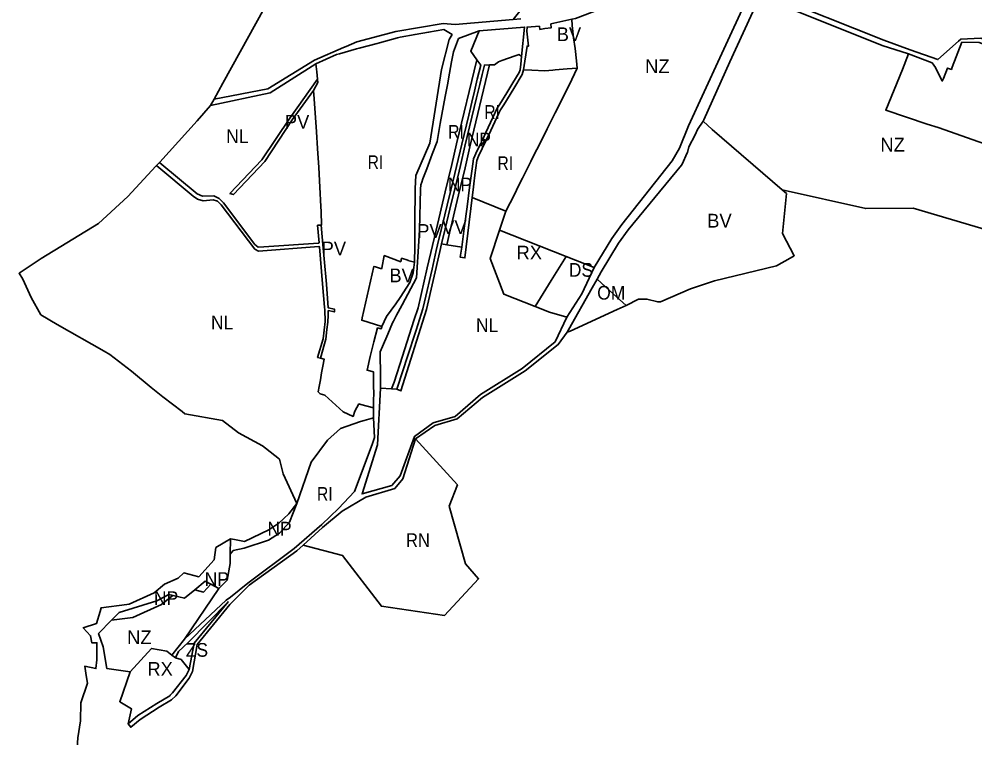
# Model space of a CAD drawing. Extents: x -650451 to -642268, y -1075216 to -1066610.
# Drawn here: x -649080 to -648035, y -1074440 to -1073654 of the extents above; entities that cross this region are included whole.
import ezdxf

# ---------------------------------------------------------------- set-up
doc = ezdxf.new("R2010")
doc.units = 0
doc.header["$LTSCALE"] = 6
doc.layers.add('1', color=7, linetype='Continuous', lineweight=35)
doc.layers.add('2', color=7, linetype='Continuous')
doc.layers.add('3', color=7, linetype='Continuous')

msp = doc.modelspace()

# ---------------------------------------------------------------- linework, layer by layer
at = {"layer": '1'}
for p, q in [((-648539.599, -1073654.802), (-648531.31, -1073654.08)), ((-648870.25, -1073748.67), (-648866.38, -1073741.66)), ((-648929.63, -1073814.73), (-648925.79, -1073810.52)), ((-648584.31, -1073849.37), (-648547.45, -1073864.3)), ((-648554.42, -1073885.092), (-648547.45, -1073864.3)), ((-648481.749, -1073913.76), (-648554.42, -1073885.092)), ((-648617.72, -1073900.06), (-648612.186, -1073900.905)), ((-648612.186, -1073900.905), (-648595.78, -1073903.41)), ((-648451.05, -1073925.87), (-648481.749, -1073913.76)), ((-648684.45, -1074057.86), (-648672.336, -1074058.391)), ((-648672.336, -1074058.391), (-648666.67, -1074058.64)), ((-648692.12, -1074079.16), (-648692.23, -1074090.17)), ((-648848.696, -1074238.993), (-648848.28, -1074222.49)), ((-648861.07, -1074276.59), (-648898.66, -1074332.22)), ((-648870.041, -1074271.933), (-648861.07, -1074276.59)), ((-648912.4, -1074349.53), (-648898.66, -1074332.22)), ((-648912.4, -1074349.53), (-648908.69, -1074352.43))]:
    msp.add_line(p, q, dxfattribs=at)
for points in [[(-648426.547, -1072954.108), (-648432.527, -1072969.463), (-648443.591, -1072965.983), (-648451.657, -1072977.25), (-648456.2, -1072989.149), (-648457.123, -1072993.118), (-648461.979, -1073045.585), (-648460.355, -1073048.753), (-648461.973, -1073052.688), (-648463.036, -1073057.011), (-648465.708, -1073085.876), (-648484.661, -1073162.812), (-648490.539, -1073212.35), (-648481.853, -1073287.675), (-648489.355, -1073326.567), (-648492.485, -1073357.358), (-648491.34, -1073364.805), (-648477.028, -1073398.055), (-648464.929, -1073407.031), (-648453.228, -1073408.349), (-648463.838, -1073440.559), (-648513.627, -1073589.927), (-648532.252, -1073645.567), (-648539.599, -1073654.802)], [(-648756.32, -1073542.14), (-648856.8, -1073724.29), (-648866.38, -1073741.66)], [(-647995.52, -1073610.74), (-648019.06, -1073678.66), (-648028.46, -1073675.12), (-648050.36, -1073676.05), (-648052.79, -1073678.24), (-648075.28, -1073698.47), (-648105.45, -1073687.74), (-648134.54, -1073677.38), (-648260.65, -1073626.84), (-648267.43, -1073624.12), (-648245.341, -1073575.152)], [(-648451.05, -1073925.87), (-648431.83, -1073894.14), (-648420.84, -1073878.8), (-648365.76, -1073809.23), (-648357.64, -1073795.36), (-648347.94, -1073770.87), (-648313.62, -1073696.79), (-648280.37, -1073624.46), (-648288.67, -1073621.32), (-648351.02, -1073597.76), (-648430.17, -1073638.14), (-648471.47, -1073653.64), (-648475.51, -1073654.52)], [(-648107.38, -1073692.13), (-648136.3, -1073683), (-648269.77, -1073629.31), (-648271.26, -1073632.62), (-648302.52, -1073701.11), (-648331.05, -1073764.33), (-648331.74, -1073765.85)], [(-648866.38, -1073741.66), (-648807.74, -1073730.53), (-648756.81, -1073699.03), (-648725.01, -1073685.42), (-648721.94, -1073684.11), (-648710.31, -1073679.13), (-648667.8, -1073668), (-648616.19, -1073659.15), (-648602.91, -1073660.32), (-648539.599, -1073654.802)], [(-648530.35, -1073695.22), (-648527, -1073663.06), (-648576.53, -1073667.04)], [(-648528.25, -1073709.77), (-648524.28, -1073683.81), (-648522.58, -1073683.79), (-648524.39, -1073667.36), (-648524.35, -1073663.01), (-648510.89, -1073662.14), (-648510.36, -1073665.55), (-648504.79, -1073664.56), (-648497.81, -1073663.79), (-648498.28, -1073659.51), (-648475.51, -1073654.52)], [(-648469.41, -1073707.95), (-648470.23, -1073699.85), (-648471.6, -1073686.38), (-648473.61, -1073674.84), (-648474.88, -1073661.27), (-648475.51, -1073654.52)], [(-648755.2, -1073703.08), (-648732.59, -1073692.97), (-648729.32, -1073692.19), (-648710.57, -1073686.87), (-648708.01, -1073686.07), (-648688.25, -1073680.78), (-648685.54, -1073680.08), (-648665.79, -1073674.74), (-648662.97, -1073673.94), (-648646.67, -1073670.98), (-648632.02, -1073668.57), (-648615.27, -1073665.71), (-648606.25, -1073671.21), (-648609.29, -1073676.43), (-648617.92, -1073709.22), (-648630.49, -1073790.01), (-648645.75, -1073825.15), (-648646.65, -1073839.57), (-648647.12, -1073876.95), (-648647, -1073902.95), (-648647.51, -1073920.03)], [(-648684.45, -1074057.86), (-648684.54, -1074045.27), (-648684.73, -1074017.9), (-648682.3, -1074012.13), (-648676.63, -1073998.7), (-648671.39, -1073986.27), (-648670.38, -1073984.38), (-648667.03, -1073978.07), (-648665.26, -1073974.76), (-648660.99, -1073966.72), (-648645.26, -1073937.15), (-648642.56, -1073896.9), (-648641.73, -1073884.56), (-648640.88, -1073840.35), (-648640.57, -1073835.5), (-648639.47, -1073832.58), (-648638.13, -1073829.03), (-648633.93, -1073817.85), (-648627.89, -1073801.82), (-648622.75, -1073788.17), (-648619.12, -1073768.29), (-648613.75, -1073738.92), (-648611.39, -1073726.03), (-648609.1, -1073713.49), (-648606.81, -1073700.98), (-648604.83, -1073690.12), (-648599.18, -1073675.54), (-648576.53, -1073667.04)], [(-648579.272, -1073698.648), (-648585.92, -1073689.3), (-648576.53, -1073667.04)], [(-648107.38, -1073692.13), (-648081.62, -1073702.08), (-648077.83, -1073707.36), (-648070.53, -1073722.09), (-648068.98, -1073719.26), (-648064.72, -1073707.89), (-648060.55, -1073709.31), (-648059.54, -1073706.72), (-648049.05, -1073679.67), (-648030.35, -1073679.74), (-648020.84, -1073683.33), (-648023.29, -1073689.72), (-648018, -1073691.73)], [(-648595.78, -1073903.41), (-648592.72, -1073880.34), (-648589.95, -1073859.49), (-648587.17, -1073838.52), (-648584.46, -1073818.12), (-648582.98, -1073806.96), (-648578.71, -1073797.92), (-648578.22, -1073796.89), (-648574.96, -1073789.98), (-648572.59, -1073790.95), (-648570.56, -1073786.33), (-648572.8, -1073785.4), (-648569.35, -1073778.1), (-648561.63, -1073761.75), (-648556.87, -1073751.68), (-648554.26, -1073747.43), (-648546.5, -1073734.76), (-648539.92, -1073724.04), (-648532.96, -1073712.69), (-648531.85, -1073709.63), (-648531.2, -1073703.4), (-648530.35, -1073695.22)], [(-648530.35, -1073695.22), (-648532.79, -1073693.1), (-648537.26, -1073694.43), (-648544.6, -1073696.88), (-648552.06, -1073699.58), (-648555.55, -1073701.12), (-648559.97, -1073704.24), (-648565.224, -1073704.393)], [(-648107.38, -1073692.13), (-648113.89, -1073709.39), (-648132.29, -1073753.96), (-648086.94, -1073768.97), (-648074.98, -1073772.93), (-648030.44, -1073788.51), (-648007.95, -1073796.14), (-647983.68, -1073804.37), (-647919.33, -1073826.21), (-647915.79, -1073796.07), (-647911.96, -1073765.02), (-647907.9, -1073732.08)], [(-648870.25, -1073748.67), (-648805.08, -1073734.98), (-648755.2, -1073703.08)], [(-648755.2, -1073703.08), (-648754.27, -1073711.87), (-648753.44, -1073719.78)], [(-648579.272, -1073698.648), (-648601.309, -1073790.592), (-648606.633, -1073813.202), (-648613.86, -1073842.943), (-648623.827, -1073884.957), (-648633.591, -1073926.228), (-648643.415, -1073969.782), (-648647.944, -1073983.639), (-648660.613, -1074022.822), (-648669.584, -1074051.005), (-648672.336, -1074058.391)], [(-648666.67, -1074058.64), (-648659.85, -1074037.72), (-648655.5, -1074024.36), (-648645.7, -1073994.3), (-648638.15, -1073971.13), (-648636.34, -1073963.19), (-648628.21, -1073927.61), (-648623.58, -1073907.34), (-648622.06, -1073901.02), (-648617.77, -1073883.09), (-648616.76, -1073878.91), (-648611.69, -1073857.74), (-648607.72, -1073841.19), (-648607.4, -1073839.84), (-648595.71, -1073791.1), (-648588.06, -1073759.19), (-648584.69, -1073745.15), (-648581.82, -1073733.14), (-648578.69, -1073720.11), (-648574.99, -1073704.67), (-648579.272, -1073698.648)], [(-648617.72, -1073900.06), (-648613.78, -1073883.59), (-648606.83, -1073854.48), (-648601.98, -1073834.2), (-648597.23, -1073814.32), (-648592.17, -1073793.18), (-648579.57, -1073740.47), (-648576.05, -1073725.82), (-648573.46, -1073714.88), (-648571.72, -1073707.63), (-648570.99, -1073704.56), (-648565.224, -1073704.393)], [(-648565.224, -1073704.393), (-648586.715, -1073794.059), (-648592.044, -1073816.692), (-648599.275, -1073846.445), (-648609.231, -1073888.415), (-648612.186, -1073900.905)], [(-648528.25, -1073709.77), (-648529.55, -1073714.78), (-648538.89, -1073729.99), (-648549.87, -1073747.88), (-648553.25, -1073753.38), (-648555.09, -1073757.27), (-648559.48, -1073766.56), (-648563.99, -1073776.12), (-648573.26, -1073795.74), (-648577.28, -1073804.24), (-648579.37, -1073808.67), (-648581.35, -1073824.95), (-648582.51, -1073834.53), (-648583.27, -1073840.83), (-648584.31, -1073849.37)], [(-648547.45, -1073864.3), (-648538.19, -1073845.84), (-648533.57, -1073836.64), (-648529.29, -1073828.1), (-648524.62, -1073818.8), (-648520.19, -1073809.96), (-648515.65, -1073800.92), (-648511.53, -1073792.7), (-648502.33, -1073774.36), (-648498.26, -1073766.24), (-648493.51, -1073756.79), (-648489.2, -1073748.19), (-648475.3, -1073720.49), (-648469.41, -1073707.95)], [(-648528.25, -1073709.77), (-648519.16, -1073710.12), (-648504.96, -1073710.66), (-648496.04, -1073709.98), (-648493.74, -1073709.81), (-648480.48, -1073708.79), (-648469.41, -1073707.95)], [(-648757.6, -1073732.5), (-648780.94, -1073764.27), (-648811.07, -1073809.84), (-648845.26, -1073846.18), (-648849.03, -1073844.76), (-648814.24, -1073808.28), (-648783.45, -1073762.42), (-648753.44, -1073719.78)], [(-648757.6, -1073732.5), (-648753.02, -1073723.7), (-648753.44, -1073719.78)], [(-648749.26, -1073879.41), (-648748.83, -1073879.38), (-648749.32, -1073864.48), (-648749.63, -1073859.01), (-648750.84, -1073837.88), (-648752.06, -1073816.42), (-648753.25, -1073795.67), (-648754.49, -1073777.63), (-648757, -1073741.26), (-648757.6, -1073732.5)], [(-647689.67, -1073774.49), (-647717.68, -1073771.6), (-647728.12, -1073773.09), (-647721.69, -1073728.34), (-647732.07, -1073752.15), (-647739.16, -1073768.4), (-647766.61, -1073768.57), (-647775.05, -1073812.14), (-647793.19, -1073831.83), (-647842.43, -1073858.83), (-647844.57, -1073882.82), (-647885.89, -1073905.24), (-647919.64, -1073892.92), (-647948.47, -1073899.97), (-647966.84, -1073901.04), (-648102.19, -1073861.13), (-648154.13, -1073861.48), (-648245.45, -1073841.08)], [(-648925.79, -1073810.52), (-648884.88, -1073765.58), (-648870.25, -1073748.67)], [(-648331.74, -1073765.85), (-648337.91, -1073774.87), (-648340.74, -1073780.66), (-648347.38, -1073793.82), (-648349.12, -1073800.06), (-648349.58, -1073801.08), (-648354.57, -1073812.08), (-648355.37, -1073813.85), (-648413.91, -1073884.54), (-648424.51, -1073899.37), (-648443.35, -1073930.53), (-648447.77, -1073938.64)], [(-648331.74, -1073765.85), (-648322.08, -1073775.04), (-648245.45, -1073841.08)], [(-648775.93, -1074183.91), (-648790.86, -1074151.18), (-648795.07, -1074135.39), (-648810.15, -1074123.44), (-648813.45, -1074120.68), (-648839.7, -1074106.68), (-648857.12, -1074092.9), (-648898.23, -1074085.75), (-648901.36, -1074083.32), (-648922.26, -1074067.06), (-648935, -1074057.16), (-648956.81, -1074039.24), (-648980.26, -1074020.98), (-648986.44, -1074017.43), (-649037.74, -1073987.98), (-649055.82, -1073977.54), (-649066.5, -1073958.76), (-649075.48, -1073938.46), (-649079.5, -1073932.07), (-649055.44, -1073915.89), (-648992.83, -1073877.83), (-648960.55, -1073848.32), (-648930.07, -1073815.22), (-648929.63, -1073814.73)], [(-648750.04, -1074025), (-648753.25, -1074024.17), (-648747.25, -1074003.7), (-648745.15, -1073984.75), (-648745.49, -1073972.04), (-648745.56, -1073969.15), (-648747.74, -1073943.79), (-648751.23, -1073903.16), (-648751.99, -1073902.72), (-648818.02, -1073907.85), (-648821.85, -1073905.87), (-648858.52, -1073857.16), (-648862.67, -1073853.45), (-648867.32, -1073851.76), (-648878.37, -1073852.91), (-648884.44, -1073851.12), (-648889.36, -1073847.76), (-648928.87, -1073814.72), (-648929.63, -1073814.73)], [(-648749.26, -1073879.41), (-648753.25, -1073879.63), (-648751.62, -1073898.7), (-648752.29, -1073899.23), (-648811.9, -1073903.16), (-648818.3, -1073903.58), (-648821.69, -1073900.68), (-648855.98, -1073855.05), (-648860.86, -1073850.34), (-648866.7, -1073847.53), (-648879.07, -1073847.84), (-648884.94, -1073845.41), (-648925.7, -1073811.25), (-648925.79, -1073810.52)], [(-648416.09, -1073967.48), (-648402.35, -1073960.34), (-648393.32, -1073960.33), (-648381.56, -1073963.36), (-648378.47, -1073963.46), (-648345.65, -1073948.97), (-648319.3, -1073940.41), (-648251.71, -1073923.92), (-648236.64, -1073915.49), (-648232.32, -1073912.96), (-648244.96, -1073888.56), (-648240.9, -1073844.99), (-648245.45, -1073841.08)], [(-648584.31, -1073849.37), (-648592.33, -1073915.34), (-648597.26, -1073914.57), (-648595.78, -1073903.41)], [(-648750.04, -1074025), (-648745.79, -1074009.12), (-648744.41, -1074004), (-648743.07, -1073993.69), (-648742, -1073985.49), (-648741.82, -1073977.79), (-648741.7, -1073972.86), (-648734.86, -1073974.34), (-648734.93, -1073972.34), (-648734.96, -1073971.34), (-648741.63, -1073969.96), (-648743.69, -1073944.2), (-648746.08, -1073916.36), (-648747.09, -1073904.68), (-648747.45, -1073900.56), (-648748.15, -1073892.33), (-648749.26, -1073879.41)], [(-648554.42, -1073885.092), (-648564.75, -1073915.91), (-648549.76, -1073954.86), (-648515.333, -1073968.584)], [(-648617.72, -1073900.06), (-648619.68, -1073908.23), (-648634.22, -1073971.89), (-648662.25, -1074060.63), (-648666.67, -1074058.64)], [(-648647.51, -1073920.03), (-648654.59, -1073918.14), (-648654.46, -1073917.64), (-648661.41, -1073915.75), (-648662.31, -1073919.6), (-648680.4, -1073912.86), (-648682.93, -1073926.51), (-648683.44, -1073927.2), (-648689.85, -1073925.22), (-648691.73, -1073924.54), (-648693.55, -1073932.59), (-648695.41, -1073940.87), (-648697.22, -1073948.87), (-648704.39, -1073980.66), (-648705.04, -1073983.53), (-648682.89, -1073990.36)], [(-648515.333, -1073968.584), (-648498, -1073940), (-648481.749, -1073913.76)], [(-648647.51, -1073920.03), (-648648.72, -1073931.63), (-648652.61, -1073942.22), (-648663, -1073958.65), (-648667.69, -1073965.44), (-648677.95, -1073979.44), (-648682.89, -1073990.36)], [(-648480.86, -1073980.25), (-648464.44, -1073954.69), (-648451.05, -1073925.87)], [(-648480.31, -1073996.63), (-648478.94, -1073993.79), (-648453.11, -1073948.16), (-648447.77, -1073938.64)], [(-648416.09, -1073967.48), (-648430.24, -1073954.59), (-648447.77, -1073938.64)], [(-648515.333, -1073968.584), (-648499.84, -1073974.76), (-648480.86, -1073980.25)], [(-648416.09, -1073967.48), (-648425.92, -1073971.61), (-648477.31, -1073995.35), (-648480.31, -1073996.63)], [(-648480.86, -1073980.25), (-648493.48, -1074007.05), (-648529.55, -1074036.36), (-648575.11, -1074064.49), (-648603.03, -1074088.66), (-648626.96, -1074095.47), (-648647.42, -1074110.4), (-648662.86, -1074153.36), (-648672.26, -1074164.18), (-648704.55, -1074173.23), (-648687.94, -1074119.5), (-648684.45, -1074057.86)], [(-648682.89, -1073990.36), (-648683.06, -1073990.83), (-648683.78, -1073992.85), (-648687.67, -1073991.84), (-648691.78, -1074007.15), (-648695.72, -1074023.13), (-648699.17, -1074038.2), (-648692.27, -1074039.98), (-648692.23, -1074047.88), (-648692.18, -1074055.75), (-648692.17, -1074057.75), (-648691.93, -1074061.16), (-648691.95, -1074063.2), (-648691.95, -1074063.59), (-648692.03, -1074070.97), (-648692.04, -1074071.48), (-648692.12, -1074079.16)], [(-648646.42, -1074113.19), (-648624.97, -1074098.4), (-648600.57, -1074091.13), (-648573, -1074067.89), (-648526.42, -1074038.86), (-648490.29, -1074010.13), (-648480.31, -1073996.63)], [(-648750.04, -1074025), (-648746.05, -1074026.17), (-648747.5, -1074033.74), (-648748.85, -1074041.09), (-648750.22, -1074048.45), (-648751.57, -1074055.82), (-648752.57, -1074061.85), (-648750.31, -1074064.07), (-648745.35, -1074065.36), (-648725.36, -1074083.48), (-648714.48, -1074088.54), (-648712.7, -1074083.01), (-648708.17, -1074075), (-648706.15, -1074075.52), (-648692.12, -1074079.16)], [(-648898.66, -1074332.22), (-648853.15, -1074289.37), (-648848.34, -1074286.15), (-648829.66, -1074270.99), (-648778.97, -1074232.99), (-648748.74, -1074206.61), (-648730.34, -1074189.22), (-648712.77, -1074170.51), (-648693.71, -1074119.17), (-648690.92, -1074111.64), (-648692.23, -1074090.17)], [(-648692.23, -1074090.17), (-648702.41, -1074093.15), (-648706.43, -1074094.32), (-648728.35, -1074101.69), (-648742.6, -1074114.47), (-648760.17, -1074138.5), (-648775.93, -1074183.91)], [(-648646.42, -1074113.19), (-648660.16, -1074156.75), (-648669.01, -1074167.27), (-648700.45, -1074176.73), (-648726.23, -1074192.02), (-648747.74, -1074210.12), (-648768.94, -1074229.25)], [(-648768.94, -1074229.25), (-648725.93, -1074240.58), (-648683.5, -1074296.12), (-648614.6, -1074306.17), (-648577.25, -1074266.06), (-648591.67, -1074249.72), (-648609.49, -1074186.61), (-648600.53, -1074163.47), (-648646.42, -1074113.19)], [(-648775.93, -1074183.91), (-648783.863, -1074204.056), (-648794.902, -1074216.219), (-648807.065, -1074223.704), (-648833.449, -1074232.685), (-648845.424, -1074235.305), (-648848.696, -1074238.993)], [(-648848.28, -1074222.49), (-648844.05, -1074223.24), (-648833.11, -1074225.2), (-648806.55, -1074212.62), (-648795.65, -1074205.35), (-648784.8, -1074195.26), (-648775.93, -1074183.91)], [(-648848.28, -1074222.49), (-648864.54, -1074231.96), (-648866.44, -1074245.34), (-648882.93, -1074263.85), (-648899.31, -1074259.67), (-648905.51, -1074265.56), (-648920.61, -1074272.01), (-648931.76, -1074281.48), (-648959.38, -1074293.74), (-648961.69, -1074294.05), (-648989.82, -1074297.79), (-648991.03, -1074301.92), (-648994.85, -1074314.87), (-649009.49, -1074319.57), (-649001.38, -1074328.31), (-648999.92, -1074336.1), (-648994.52, -1074336.05), (-648994.4, -1074354.54), (-648995.62, -1074364.26), (-649007.82, -1074361.7), (-649006.15, -1074371.86), (-649004.8, -1074380.03), (-649012.16, -1074401.51), (-649012.49, -1074421.43), (-649015.17, -1074439.77), (-649016.78, -1074461.38)], [(-648960.37, -1074424.7), (-648957.5, -1074428.36), (-648947.1, -1074419.87), (-648926.44, -1074406.36), (-648912.91, -1074398.48), (-648908.35, -1074394.15), (-648893.8, -1074374.63), (-648890.01, -1074367.45), (-648884.95, -1074337.83), (-648849.36, -1074294.21), (-648827.96, -1074273.15), (-648775.91, -1074235.53), (-648768.94, -1074229.25)], [(-648848.696, -1074238.993), (-648848.96, -1074249.46), (-648852.22, -1074267.61), (-648861.07, -1074276.59)], [(-648887.619, -1074278.134), (-648876.21, -1074268.73), (-648870.041, -1074271.933)], [(-648910.988, -1074284.211), (-648898.58, -1074287.17), (-648887.619, -1074278.134)], [(-648870.041, -1074271.933), (-648877.799, -1074280.64), (-648887.619, -1074278.134)], [(-648910.988, -1074284.211), (-648915.73, -1074283.08), (-648929.03, -1074290.14), (-648970.3, -1074302.9), (-648978.575, -1074311.426)], [(-648910.988, -1074284.211), (-648912.63, -1074284.912), (-648923.698, -1074294.313), (-648955.265, -1074308.325), (-648978.575, -1074311.426)], [(-648908.69, -1074352.43), (-648905.14, -1074345.43), (-648894.65, -1074335.72), (-648851.16, -1074291.13), (-648888.06, -1074336.58), (-648893.77, -1074365.14)], [(-648958.23, -1074367.89), (-648983.61, -1074364.28), (-648987.52, -1074340.58), (-648992.73, -1074326.01), (-648978.575, -1074311.426)], [(-648958.23, -1074367.89), (-648934.81, -1074342.16), (-648917.94, -1074345.05), (-648912.4, -1074349.53)], [(-648893.77, -1074365.14), (-648902.52, -1074354.41), (-648908.69, -1074352.43)], [(-648958.23, -1074367.89), (-648969.59, -1074400.58), (-648956.69, -1074408.11), (-648960.37, -1074424.7)], [(-648893.77, -1074365.14), (-648896.94, -1074371.93), (-648911.88, -1074390.74), (-648914.34, -1074393.35), (-648914.83, -1074393.86), (-648928.85, -1074402.42), (-648949.75, -1074415.44), (-648960.37, -1074424.7)]]:
    msp.add_lwpolyline(points, dxfattribs=at)

# ---------------------------------------------------------------- texts
at = {"layer": '2'}
for s, p in [('BV', (-648491.949, -1073678.33)), ('NZ', (-648395.308, -1073713.355)), ('PV', (-648789.092, -1073774.078)), ('NZ', (-648138.176, -1073799.066)), ('BV', (-648327.423, -1073882.136)), ('PV', (-648644.391, -1073893.397)), ('VV', (-648617.063, -1073889.214)), ('PV', (-648748.887, -1073912.574)), ('BV', (-648674.818, -1073941.982)), ('NZ', (-648961.476, -1074337.53)), ('RX', (-648939.32, -1074372.08))]:
    msp.add_text(s, height=15, dxfattribs=at).set_placement(p)
for s, width, p in [('RI', 0.85, (-648571.07, -1073763.35)), ('NL', 0.95, (-648853.158, -1073789.894)), ('RI', 0.85, (-648610.52, -1073785.07)), ('RI', 0.85, (-648698.56, -1073818.3)), ('RI', 0.85, (-648556.63, -1073819.36)), ('OM', 0.95, (-648447.67, -1073960.89)), ('NL', 0.95, (-648869.784, -1073993.457)), ('NL', 0.95, (-648580.14, -1073996.412)), ('RI', 0.85, (-648753.9, -1074180.79)), ('ZS', 0.95, (-648897.336, -1074351.31))]:
    msp.add_text(s, height=15, dxfattribs=dict(at, width=width)).set_placement(p)
at = {"layer": '3'}
for s, width, p in [('NP', 0.95, (-648590.177, -1073793.321)), ('NP', 0.95, (-648610.933, -1073842.616)), ('DS', 0.95, (-648478.691, -1073935.932)), ('NP', 0.95, (-648808.114, -1074218.817)), ('RN', 0.9, (-648656.62, -1074231.369)), ('NP', 0.95, (-648876.684, -1074273.858)), ('NP', 0.95, (-648932.095, -1074294.799))]:
    msp.add_text(s, height=15, dxfattribs=dict(at, width=width)).set_placement(p)
msp.add_text('RX', height=15, dxfattribs=at).set_placement((-648535.777, -1073917.027))

doc.saveas('drawing.dxf')
